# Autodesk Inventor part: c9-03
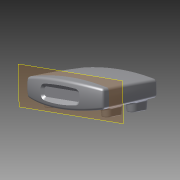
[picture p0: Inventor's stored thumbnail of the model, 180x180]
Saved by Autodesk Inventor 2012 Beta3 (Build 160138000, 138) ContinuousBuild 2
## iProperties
Created: 2010-12
Part Number: c9-03
Material: Default
Document SubType Name: Modeling
Designer: Beta-8540w
Density: 1 g/cm^3
Author: Beta-8540w
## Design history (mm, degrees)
sketch "Sketch1"
  geometry: L1 (-60, -12)-(60, -12); L2 (60, -12)-(60, 12); L3 (60, 12)-(-60, 12); L4 (-60, 12)-(-60, -12); A1 r 350 centre (0, -332.819) between (60, 12) and (-60, 12); A2 r 350 centre (0, 332.819) between (-60, -12) and (60, -12); 3 further points
  constraints: 8 end point, 4 point on circle, 2 centre point, 2 midpoint, 2 parallel, 1 equal radius, 1 horizontal, 1 horizontal alignment, 1 perpendicular, 1 vertical alignment
  dimensions: "d0" = 120 distance of L3.end L2.end; "d1" = 24 distance of L2.end L1.end; "d2" = 350 radius of A1
workplane "Work Plane4"
sketch "Sketch5"
  geometry: L1 (-60, 12)-(-60, -12) reference; L2 (60, -12)-(60, 12) reference; L3 (-58, 10.314)-(-58, -10.314); L4 (58, -10.314)-(58, 10.314); A1 r 350 centre (0, 332.819) between (-60, -12) and (60, -12) reference; A2 r 350 centre (0, -332.819) between (60, 12) and (-60, 12) reference; A3 r 348 centre (0, 332.819) between (-58, -10.314) and (58, -10.314); A4 r 348 centre (0, -332.819) between (58, 10.314) and (-58, 10.314); 1 further point
  constraints: 4 end point, 4 point on circle, 2 centre point, 3 other
  dimensions: "d37" = 2 distance between parallel lines of L2 L4
sketch "Sketch6"
  geometry: L1 (-60, 0)-(60, 0); L2 (60, 0)-(58.843, 22.085); L3 (-60, 0)-(-58.779, 23.307); A1 r 691.758 centre (630.81, -36.204) between (-60, 0) and (-58, -100); A2 r 691.758 centre (-630.81, -36.204) between (58, -100) and (60, 0); 1 further point
  constraints: 6 end point, 4 point on circle, 2 centre point, 2 tangent, 1 horizontal
  dimensions: "d53" = 87 deg angle of L1 L3; "d54" = 87 deg angle of L1 L2 (= d53)
sketch "Sketch7"
  geometry: L1 (17.181, 0)-(12, 0) reference; L2 (15.181, -100)-(10.314, -100) reference; L3 (17.181, 0)-(16.768, 11.838); A1 r 911.322 centre (-893.585, -31.805) between (15.181, -100) and (17.181, 0); 1 further point
  constraints: 2 end point, 2 point on circle, 1 centre point, 1 tangent
  dimensions: "d56" = 88 deg angle of L1 L3
feature "LoftSrf2" sketch "Sketch5", "Sketch6", "Sketch7" dims "d57" = 0, "d58" = 90 deg, "d59" = 0, "d60" = 90 deg, "d61" = 0, "d62" = 90 deg, "d63" = 0, "d64" = 90 deg, "d65" = 0, "d66" = 90 deg
sketch "Sketch2"
  geometry: L1 (-75, -16)-(75, -16); L2 (-75, -60)-(75, -60); A1 r 183.781 centre (0, -183.781) between (75, -16) and (-75, -16); 2 further points
  constraints: 4 end point, 3 point on circle, 1 centre point, 1 coincident, 1 horizontal, 1 parallel
  dimensions: "d5" = 16 distance from line of point (0, 0) L1; "d7" = 60 distance from line of point (0, 0) L2; "d55" = 150 distance of L1.start L1.end
feature "RevolutionSrf1" sketch "Sketch2" dims angle "d8" = 40 deg
patch "Boundary Patch1" dims "d13" = 0, "d67" = 0, "d68" = 0, "d69" = 0, "d70" = 0
workplane "Work Plane1"
sketch "Sketch3"
  geometry: L1 (52, -85)-(52, -73); L2 (38, -73)-(38, -85); A1 r 7 centre (45, -73) between (52, -73) and (38, -73); A2 r 7 centre (45, -85) between (38, -85) and (52, -85); 1 further point
  constraints: 4 end point, 4 point on circle, 4 tangent, 2 centre point, 1 parallel, 1 vertical
  dimensions: "d15" = 12 distance of L1.start L1.end; "d16" = 7 radius of A1; "d50" = 45 horizontal distance of A1.centre point (0, 0); "d51" = 85 vertical distance of point (0, 0) A2.centre
extrude_surface "ExtrusionSrf2" sketch "Sketch3" dims "d19" = 14, "d20" = 5 deg
pattern_linear "Rectangular Pattern1" dims "d23" = 90
workplane "Work Plane2"
feature "Sculpt1"
sketch "Sketch4"
  geometry: L1 (-24.5, 6)-(24.5, 6); L2 (27.5, 3)-(27.5, -3); L3 (24.5, -6)-(-24.5, -6); L4 (-27.5, -3)-(-27.5, 3); A1 r 3 centre (-24.5, 3) between (-24.5, 6) and (-27.5, 3); A2 r 3 centre (24.5, 3) between (27.5, 3) and (24.5, 6); A3 r 3 centre (24.5, -3) between (24.5, -6) and (27.5, -3); A4 r 3 centre (-24.5, -3) between (-27.5, -3) and (-24.5, -6); 6 further points
  constraints: 8 end point, 8 point on circle, 8 tangent, 6 point on line, 4 centre point, 3 equal radius, 2 midpoint, 2 parallel, 1 horizontal, 1 horizontal alignment, 1 perpendicular, 1 vertical alignment
  dimensions: "d28" = 55 distance of point (27.5, -6) point (-27.5, -6); "d29" = 12 distance of point (27.5, 6) point (27.5, -6); "d30" = 3 radius of A1
extrude_surface "ExtrusionSrf6" sketch "Sketch4" dims "d31" = 14, "d32" = 45 deg
patch "Boundary Patch2" dims "d33" = 0, "d34" = 0
fillet "Fillet1" dims "d79" = 4, "d80" = 3, "d81" = 1
feature "Sculpt2"
node "Splitting Plane 1"
shell "Shell1" dims "d83" = 2
body "Solid1"
body "Srf2"
body "Srf3"
body "Srf4"
body "Srf5"
body "Srf6"
body "Srf7"
body "Srf8"
body "Srf9"
body "Srf11"
feature "Stitch Surface1"
body "Srf12"
extrude_surface "ExtrusionSrf3"
extrude_surface "ExtrusionSrf4"
extrude_surface "ExtrusionSrf5"
other parameters: "d14" = -24, "d52" = -6
